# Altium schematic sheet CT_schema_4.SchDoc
size 321 x 262 mm
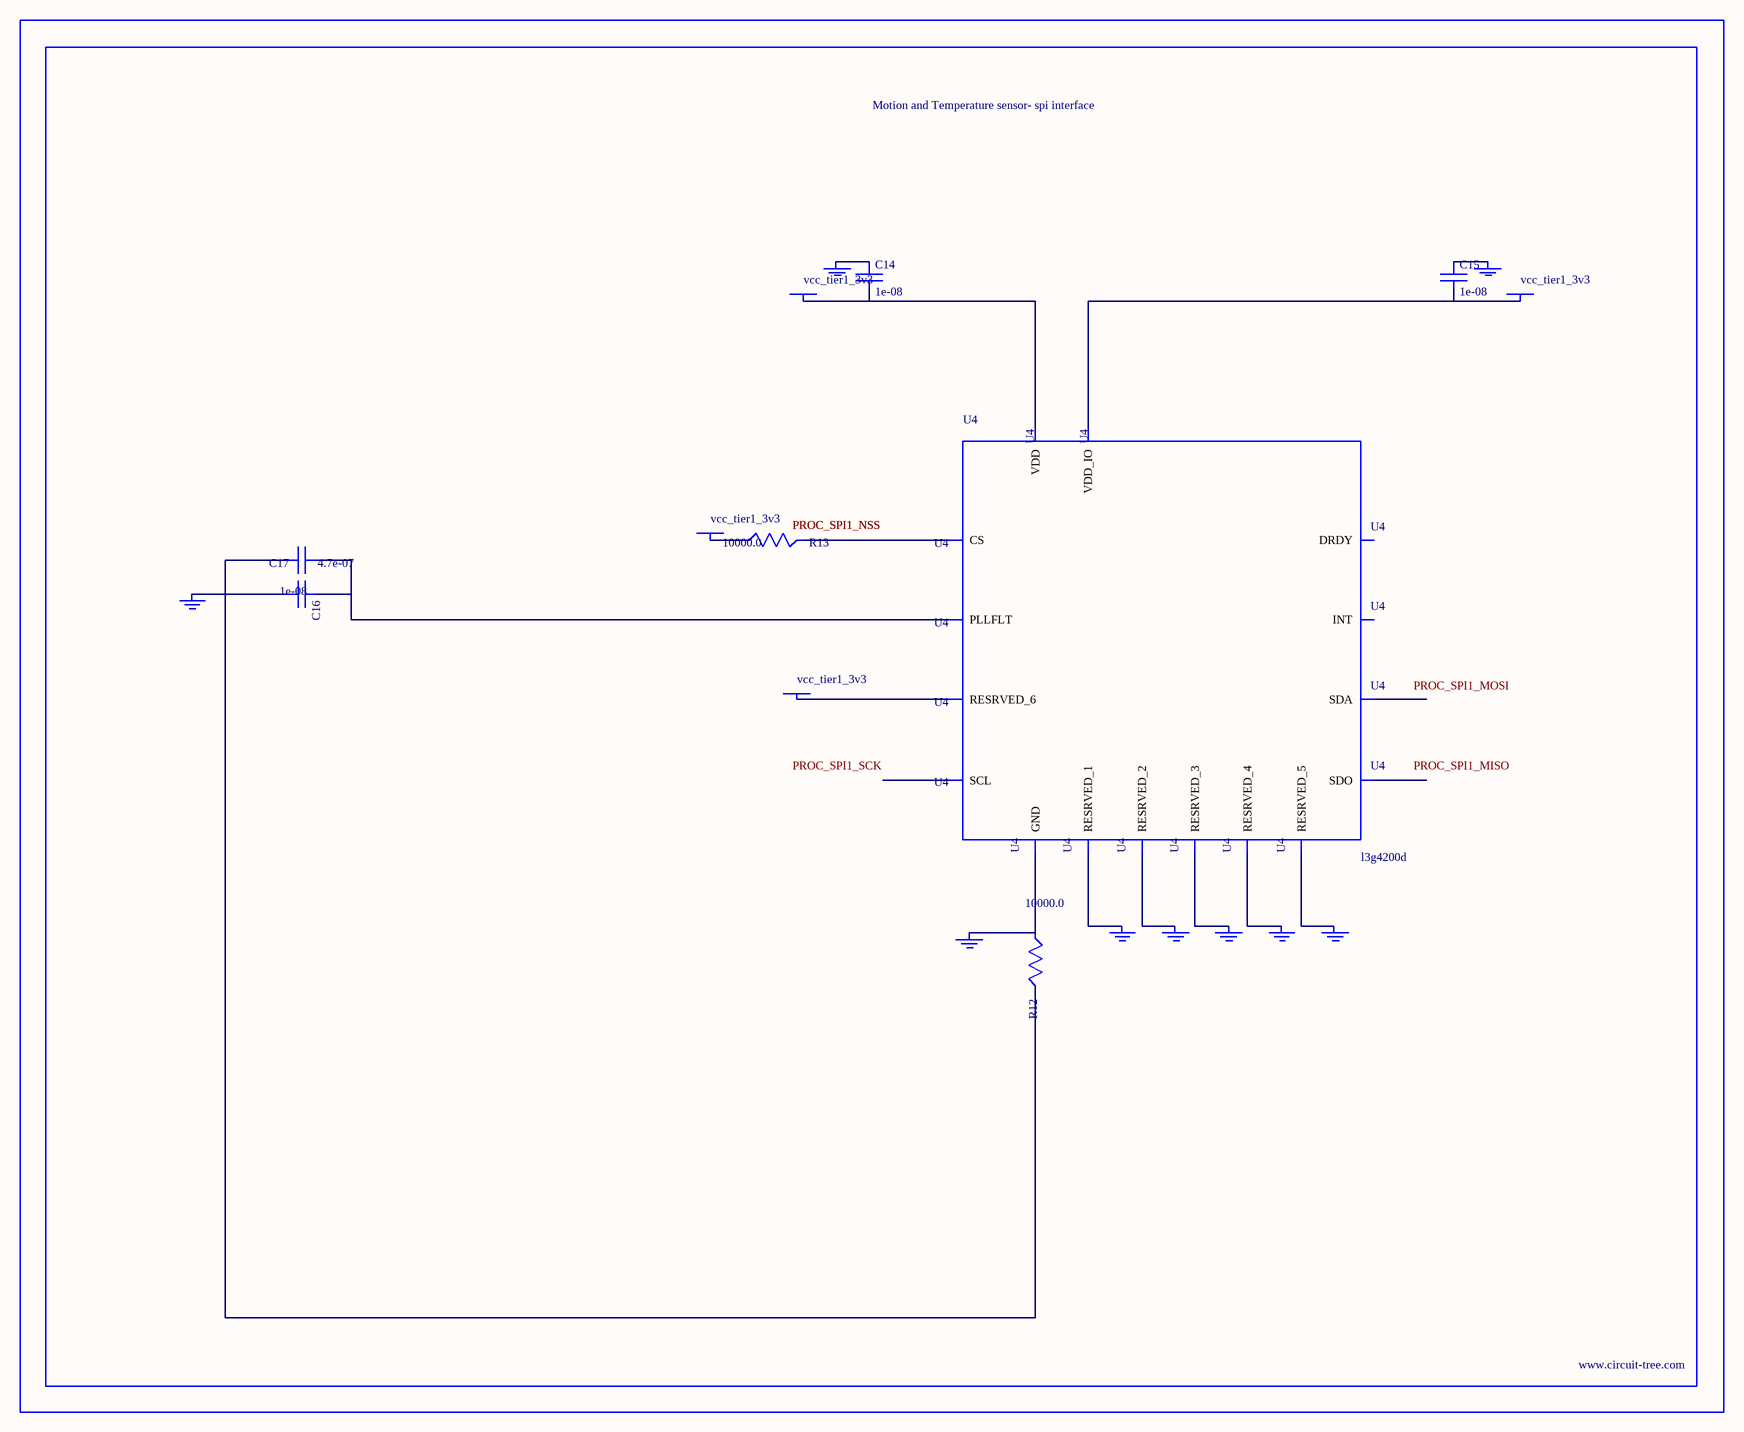
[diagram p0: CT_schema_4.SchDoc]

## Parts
BORDER3  (no value)
C14  1e-08  [C0402]
C15  1e-08  [C0402]
C16  1e-08  [C0402]
C17  4.7e-07  [C0603]
GND_INSTANCE_3_0  (no value)
GND_INSTANCE_3_1  (no value)
GND_INSTANCE_3_2  (no value)
GND_INSTANCE_3_3  (no value)
GND_INSTANCE_3_4  (no value)
GND_INSTANCE_3_5  (no value)
GND_INSTANCE_3_6  (no value)
GND_INSTANCE_3_7  (no value)
GND_INSTANCE_3_8  (no value)
POWER_INSTANCE_3_0  vcc_tier1_3v3
POWER_INSTANCE_3_1  vcc_tier1_3v3
POWER_INSTANCE_3_2  vcc_tier1_3v3
POWER_INSTANCE_3_3  vcc_tier1_3v3
R12  10000.0  [R0603]
R13  10000.0  [R0603]
U4  l3g4200d  [LGA-16]

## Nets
NetC14_1: C14.1 GND_INSTANCE_3_8.0(GND)
NetC14_2: C14.2 POWER_INSTANCE_3_3.0(PWR) U4.16(VDD)
NetC15_1: C15.1 GND_INSTANCE_3_0.0(GND)
NetC15_2: C15.2 POWER_INSTANCE_3_0.0(PWR) U4.1(VDD_IO)
NetC16_1: C16.1 C17.1 U4.14(PLLFLT)
NetC16_2: C16.2 C17.2 GND_INSTANCE_3_7.0(GND) R12.2
NetGND_INSTANCE_3_1_0: GND_INSTANCE_3_1.0(GND) U4.8(RESRVED_1)
NetGND_INSTANCE_3_2_0: GND_INSTANCE_3_2.0(GND) U4.9(RESRVED_2)
NetGND_INSTANCE_3_3_0: GND_INSTANCE_3_3.0(GND) U4.10(RESRVED_3)
NetGND_INSTANCE_3_4_0: GND_INSTANCE_3_4.0(GND) U4.11(RESRVED_4)
NetGND_INSTANCE_3_5_0: GND_INSTANCE_3_5.0(GND) U4.12(RESRVED_5)
NetGND_INSTANCE_3_6_0: GND_INSTANCE_3_6.0(GND) R12.1 U4.13(GND)
NetPOWER_INSTANCE_3_1_0: POWER_INSTANCE_3_1.0(PWR) R13.1
NetPOWER_INSTANCE_3_2_0: POWER_INSTANCE_3_2.0(PWR) U4.15(RESRVED_6)
NetR13_2: R13.2 U4.5(CS)

Not connected (* = marked no-connect by the designer): U4 2(SCL) 3(SDA) 4(SDO) 6(DRDY) 7(INT)

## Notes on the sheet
- Labels drawn without touching a wire or pin: PROC_SPI1_MISO, PROC_SPI1_MOSI, PROC_SPI1_SCK

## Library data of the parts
BORDER3 = BORDER_PAGE3
C14-C16 = C0402C103K3RAC
C17 = C0603C474K3RAC
GND_INSTANCE_3_0-GND_INSTANCE_3_8 = GND
POWER_INSTANCE_3_0-POWER_INSTANCE_3_3 = PWR
R12 R13 = RC0603JR-0710KL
